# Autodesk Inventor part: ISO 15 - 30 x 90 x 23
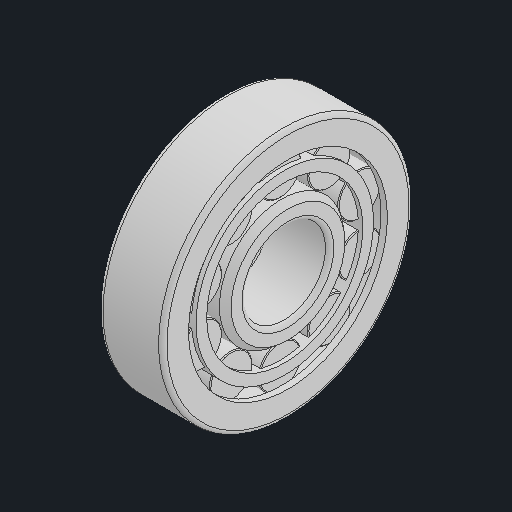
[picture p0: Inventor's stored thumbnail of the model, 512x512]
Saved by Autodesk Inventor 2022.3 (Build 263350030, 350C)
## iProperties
Created: 2020-09
Part Number: ISO 15 - 30 x 90 x 23
Material: Типовые
Document SubType Name: Modeling
Designer: Карташов
Density: 1 g/cm^3
Appearance: По умолчанию
Title: D:\мои документы\Ирина\_WorldSkills\2020_09 ФНЧ\Module A\GIVEN\ISO 15 - 30 x 90 x 23.stp
Author: Дом
Sending System: Autodesk Inventor 2021
Preprocessor: ST-DEVELOPER v18.1
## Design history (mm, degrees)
feature "Твердое тело2"
node "Твердое тело1"
